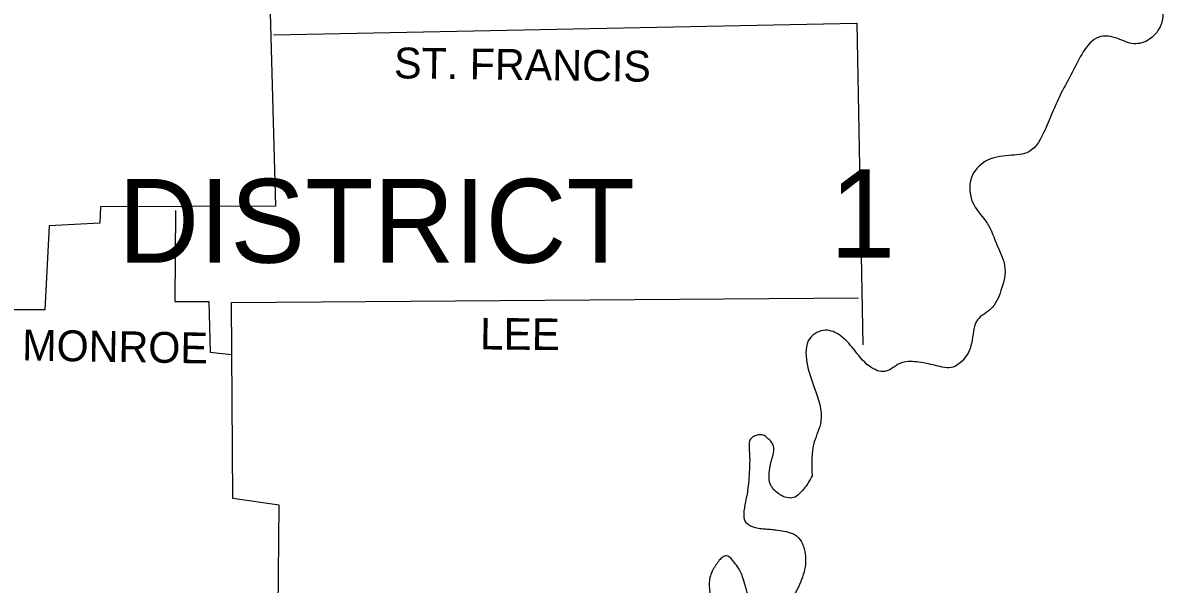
# Model space of a CAD drawing. Extents: x -33639 to 34530, y -17264 to 5867.
# Drawn here: x 3591 to 4445, y -8698 to -8278 of the extents above; entities that cross this region are included whole.
import ezdxf

# ---------------------------------------------------------------- set-up
doc = ezdxf.new("R2010")
doc.units = 0
for name, color, linetype in [('1', 7, 'Continuous'), ('2', 7, 'Continuous'), ('3', 7, 'Continuous')]:
    doc.layers.add(name, color=color, linetype=linetype)

msp = doc.modelspace()

# ---------------------------------------------------------------- linework, layer by layer
at = {"layer": '1'}
for points in [[(3772.5102953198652, -8116.2340376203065), (3780.6883585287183, -8415.005944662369), (3649.704145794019, -8415.556298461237), (3649.153791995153, -8427.664082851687), (3611.179377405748, -8429.865498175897), (3607.877254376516, -8492.60583532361), (3561.647532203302, -8492.60583532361)], [(3779.037296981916, -8286.773501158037), (4216.01824173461, -8277.967839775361)], [(4216.01824173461, -8277.967839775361), (4220.4210724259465, -8519.02281942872)], [(3705.840237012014, -8418.308067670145), (3705.289883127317, -8486.551943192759), (3730.6061595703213, -8486.551943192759), (3731.7068672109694, -8524.526357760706), (3747.6671284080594, -8526.177419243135)], [(3782.6552624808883, -8716.897825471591), (3783.4401276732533, -8638.999955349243), (3748.7678360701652, -8634.046770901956), (3747.6671284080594, -8487.102296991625), (4217.118949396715, -8483.800173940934)]]:
    msp.add_lwpolyline(points, dxfattribs=at)
for points in [[(4421.300222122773, -8071.585151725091), (4423.501637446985, -8087.545412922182), (4414.145622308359, -8104.606381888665), (4410.843499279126, -8121.667350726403), (4412.494560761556, -8138.728319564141), (4394.8832381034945, -8148.084334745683), (4379.47333070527, -8159.091411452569), (4388.278992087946, -8172.299903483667), (4404.789607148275, -8184.407687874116), (4421.300222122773, -8193.763703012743), (4431.756945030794, -8203.119718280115), (4434.508714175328, -8225.684225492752), (4437.260483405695, -8239.993425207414), (4442.76402173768, -8259.806163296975), (4444.965437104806, -8273.56500912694), (4435.059068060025, -8290.075624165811), (4423.501637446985, -8293.377747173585), (4411.393853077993, -8289.525270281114), (4397.084653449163, -8288.424562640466), (4385.5272228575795, -8299.431639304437), (4377.271915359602, -8314.84154670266), (4369.016607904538, -8330.251454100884), (4362.9627156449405, -8343.459946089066), (4356.908823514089, -8357.769145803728), (4344.801039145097, -8374.279760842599), (4329.941485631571, -8377.031530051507), (4312.330162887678, -8381.434360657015), (4301.8734399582, -8393.542145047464), (4303.52450152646, -8413.905237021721), (4313.430870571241, -8427.664082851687), (4321.135824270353, -8444.725051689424), (4326.639362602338, -8459.58460520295), (4323.887593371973, -8478.29663560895), (4316.18263967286, -8492.055481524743), (4306.2762706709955, -8500.310789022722), (4301.8734399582, -8517.922111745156), (4294.718840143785, -8531.130603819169), (4288.114594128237, -8535.533434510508), (4274.9061020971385, -8534.432726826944), (4260.5969023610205, -8531.68095757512), (4248.4891180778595, -8532.781665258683), (4236.931687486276, -8538.835557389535), (4225.374256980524, -8534.98308062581), (4213.266472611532, -8521.774588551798), (4203.360103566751, -8511.868219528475), (4192.353026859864, -8508.015742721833), (4180.795596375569, -8514.069634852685), (4178.594181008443, -8532.231311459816), (4184.097719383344, -8550.943341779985), (4189.05090385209, -8576.259618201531), (4184.097719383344, -8591.669525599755), (4182.446657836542, -8616.985801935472)], [(4182.446657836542, -8616.985801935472), (4176.839301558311, -8626.142518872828), (4173.354075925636, -8629.968216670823), (4169.788519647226, -8632.946063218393), (4159.607709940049, -8631.900198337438), (4154.44128474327, -8628.02159438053), (4152.446856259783, -8625.615408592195), (4151.076489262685, -8623.03969419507), (4150.282008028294, -8616.424934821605), (4151.076489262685, -8609.831202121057), (4151.769537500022, -8606.379750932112), (4152.792009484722, -8602.937733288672), (4153.644663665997, -8599.502738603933), (4153.828258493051, -8596.072356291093), (4151.446090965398, -8591.104456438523), (4149.384231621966, -8589.015564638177), (4147.224012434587, -8587.266694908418), (4144.204489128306, -8586.327332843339), (4140.520775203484, -8586.809036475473), (4137.299322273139, -8588.48268852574), (4135.666581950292, -8591.119171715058), (4135.351394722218, -8595.382917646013), (4135.47434529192, -8599.651441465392), (4135.693414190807, -8603.91907265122), (4135.666581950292, -8608.180140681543), (4134.565874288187, -8624.690755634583), (4133.752950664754, -8630.63622680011), (4132.550640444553, -8636.557368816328), (4131.267171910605, -8645.409490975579), (4131.228518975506, -8646.882861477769), (4131.2637512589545, -8648.355970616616), (4133.887594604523, -8652.852424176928), (4136.332989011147, -8654.454435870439), (4138.968704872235, -8655.510570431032), (4143.361232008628, -8656.416362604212), (4147.778591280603, -8656.835997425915), (4152.193838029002, -8657.143272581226), (4156.58002759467, -8657.711985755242), (4162.965734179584, -8658.792122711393), (4166.118202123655, -8659.628099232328), (4169.238165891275, -8661.014108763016), (4174.468412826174, -8666.511939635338), (4175.971373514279, -8670.016217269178), (4176.943119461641, -8673.672246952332), (4177.608761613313, -8681.424923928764), (4176.3927656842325, -8689.082154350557), (4170.338873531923, -8703.941707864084), (4161.533212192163, -8716.049492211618), (4154.802060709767, -8719.895896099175), (4151.207795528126, -8720.602523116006), (4147.774366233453, -8720.452322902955), (4141.606295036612, -8718.156427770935), (4138.855503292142, -8716.05829140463), (4136.767289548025, -8713.29772308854), (4135.259610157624, -8709.733553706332), (4134.25795405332, -8706.134989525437), (4133.410258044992, -8702.540492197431), (4132.364458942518, -8698.98852337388), (4130.390589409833, -8692.638326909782), (4127.4112743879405, -8686.330385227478), (4125.205462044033, -8683.17621605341), (4122.843679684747, -8680.207531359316), (4118.055259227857, -8676.974369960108), (4115.508946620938, -8677.829001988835), (4112.959817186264, -8680.318819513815), (4110.481816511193, -8683.750592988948), (4109.292597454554, -8685.60307897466), (4108.148890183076, -8687.431092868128), (4105.482324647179, -8697.045322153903), (4105.9474748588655, -8706.693477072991), (4106.02163556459, -8709.30490390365)]]:
    msp.add_spline(points, degree=3, dxfattribs=at)

# ---------------------------------------------------------------- texts
msp.add_text('1', height=66.04246017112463, dxfattribs=at).set_placement((4195.655149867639, -8453.5307130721))
at = {"layer": '2'}
for s, height, rotation, p in [('ST. FRANCIS', 23.108256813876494, 359.22157224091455, (3869.295325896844, -8319.244377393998)), ('LEE', 23.66631560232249, 359.4327333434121, (3933.6867245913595, -8522.324942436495)), ('MONROE', 23.108256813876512, 359.0330750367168, (3590.816285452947, -8530.580249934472))]:
    msp.add_text(s, height=height, rotation=rotation, dxfattribs=at).set_placement(p)
at = {"layer": '3'}
msp.add_text('DISTRICT', height=62.74033716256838, dxfattribs=at).set_placement((3662.9126378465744, -8457.38318996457))

doc.saveas('drawing.dxf')
